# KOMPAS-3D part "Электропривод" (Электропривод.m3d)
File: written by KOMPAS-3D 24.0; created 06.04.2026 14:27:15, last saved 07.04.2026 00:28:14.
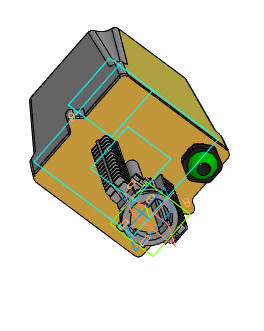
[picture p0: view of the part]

Document properties: Автор: R2D2; Полное имя файла: E:\Работа\Зайцев\Солянка\VSR1-13V-PED-F Клапан запорно-регулирующий DN.ru\DN15\DN15 Kv0.16\исходные материалы\Электропривод.m3d

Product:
- Body: Тело 1  | qty 1
    Масса: 16.873514
- Body: Тело 2  | qty 1
    Масса: 16.873514
- Body: Тело 3  | qty 1
    Масса: 16.873514
- Component [standard]: Hexagon socket head cap screw ISO 4762 - М4 x 10  | qty 1  | Материал: Не определено (density 0 kg/m3); Масса: 0.0018; Рассекать на разрезах: no; source file: C:\Program Files\ASCON\KOMPAS-3D v24\Libs\PolynomLib\DATA\vault\Methods\Kompas\3D\PLib_Screw_DIN_7984_1500.m3d
- Component [standard]: Hexagon socket head cap screw ISO 4762 - М4 x 10  | qty 1  | Материал: Не определено (density 0 kg/m3); Масса: 0.0018; Рассекать на разрезах: no
- Component [standard]: Cheese head screw ISO 7048 - М5 x 10 - H  | qty 1  | Материал: Не определено (density 0 kg/m3); Масса: 0.00255; Рассекать на разрезах: no; source file: C:\Program Files\ASCON\KOMPAS-3D v24\Libs\PolynomLib\DATA\vault\Methods\Kompas\3D\PLib_Screw_ISO_7048_1500.m3d
- Component [standard]: Cheese head screw ISO 7048 - М5 x 10 - H  | qty 1  | Материал: Не определено (density 0 kg/m3); Масса: 0.00255; Рассекать на разрезах: no
- Component [standard]: Hexagon socket set screw ISO 4026 - М4 x 10  | qty 1  | Материал: Не определено (density 0 kg/m3); Масса: 0.0007; Рассекать на разрезах: no; source file: C:\Program Files\ASCON\KOMPAS-3D v24\Libs\PolynomLib\DATA\vault\Methods\Kompas\3D\PLib_Set_Screws_ISO_1100.m3d
- Component [standard]: Hexagon socket set screw ISO 4026 - М4 x 10  | qty 1  | Материал: Не определено (density 0 kg/m3); Масса: 0.0007; Рассекать на разрезах: no
- Component [detail]: Деталь  | qty 1  | Масса: 0.134709; Автор: R2D2; source file: ручка.m3d
- Component [detail]: Деталь  | qty 1  | Масса: 0.106559; Автор: R2D2; source file: кабельный зажим.m3d
- Part/product: Электропривод
    Масса: 0.101125

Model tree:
1. Низ
2. Элемент вращения:1
     Угол 1 = 360
3. Эскиз:4  (with: Ребро.Элемент вращения:1, Грань.Элемент вращения:1)
4. Элемент выдавливания:3
     Расстояние 1 = 25
5. Эскиз:9  (with: Ребро.Элемент выдавливания:3)
6. Элемент выдавливания:6
     Расстояние 2 = 25
7. Эскиз:3  (with: Грань.Элемент вращения:1)
8. Элемент выдавливания:2
9. Эскиз:2  (with: Грань.Элемент вращения:1, Ребро.Элемент выдавливания:2)
10. Элемент выдавливания:1
11. Массив по концентрической сетке:1  (with: Элемент выдавливания:1, Эскиз:2, Грань.Элемент выдавливания:2)  (5 pattern instances)
     Шаг 2 = 360
12. Смещенная плоскость:1
     Расстояние = 269
13. Смещенная плоскость:2
     Расстояние = 125
14. крышка
15. Элемент выдавливания:4
     Расстояние 2 = 144
16. Уклон:1  (with: Грань.Элемент выдавливания:4)
     Угол уклона = 2
17. Эскиз:6  (with: Грань.Элемент выдавливания:4, Вершина.Элемент выдавливания:4)
18. Смещенная плоскость:3  (with: Грань.Элемент выдавливания:4)
     Расстояние = 114
19. Эскиз:7  (with: Ребро.Элемент выдавливания:4)
20. Элемент по сечениям:1
21. Скругление:26  (with: Ребро.Элемент выдавливания:4, Ребро.Элемент по сечениям:1, Грань.Элемент по сечениям:1)
     Радиус = 5
22. Массив по концентрической сетке:3  (with: Элемент по сечениям:1, Эскиз:6, Смещенная плоскость:3, Эскиз:7, Скругление:26)  (4 pattern instances)
     Шаг 2 = 360
23. Скругление:27  (with: Грань.Элемент выдавливания:4)
     Радиус = 5
24. уши  (with: Грань.Элемент выдавливания:4)
25. Элемент выдавливания:5
     Расстояние 2 = 15
26. Скругление:29  (with: Ребро.Элемент выдавливания:5)
     Радиус = 5
27. Эскиз:10  (with: Грань.Элемент выдавливания:4)
28. Элемент выдавливания:7
     Расстояние 1 = 0.5
29. Эскиз:11  (with: Грань.Элемент выдавливания:7, Ребро.Элемент выдавливания:4, Ребро.Скругление:26, Ребро.Элемент выдавливания:5, Ребро.Скругление:29)  (labels: Ребро.Скругление:26.Экземпляр ( 1, 4 ); Ребро.Скругление:26.Экземпляр ( 1, 3 ); Ребро.Скругление:26.Экземпляр ( 1, 2 ))
30. Элемент выдавливания:8
     Расстояние 1 = 5
31. РЕБРО  (with: Ребро.Элемент вращения:1, Ребро.Элемент выдавливания:8)
32. Элемент выдавливания:9
     Расстояние 1 = 3
33. Эскиз:13  (with: Ребро.Элемент выдавливания:9, Ребро.Элемент выдавливания:8, Грань.Элемент вращения:1, Вершина.Элемент вращения:1, Вершина.Элемент выдавливания:9, Ребро.Элемент вращения:1)
34. Элемент выдавливания:10
     Толщина стенки 2 = 2; Расстояние 1 = 20
35. Фаска:6  (with: Ребро.Элемент выдавливания:9)
     Угол = 60; Длина 1 = 10; Длина 2 = 17.3205
36. Эскиз:14  (with: Вершина.Фаска:6, Ребро.Элемент выдавливания:10)
37. Элемент выдавливания:11
     Толщина стенки 1 = 2; Расстояние 1 = 20
38. Скругление:30  (with: Ребро.Элемент выдавливания:11)
     Радиус = 2
39. Массив по сетке:1  (with: Элемент выдавливания:11, Скругление:30, Ребро.Элемент выдавливания:9)  (14 pattern instances)
     Шаг 1 = 7; Угол раствора = 90
40. Эскиз:15  (with: Ребро.Элемент выдавливания:10, Ребро.Фаска:6, Ребро.Элемент выдавливания:11)
41. Элемент выдавливания:12
     Толщина стенки 2 = 2; Расстояние 1 = 20
42. Скругление:31  (with: Ребро.Элемент выдавливания:12)
     Радиус = 2
43. маятник  (with: Ребро.Элемент выдавливания:8)
44. Элемент вращения:2
     Угол 1 = 360
45. Эскиз:17  (with: Ребро.Элемент вращения:2)
46. Элемент выдавливания:13
     Расстояние 1 = 13
47. Скругление:32  (with: Ребро.Элемент выдавливания:13)
     Радиус = 4
48. Эскиз:18  (with: Ребро.Элемент выдавливания:13)
49. Элемент выдавливания:14
     Расстояние 1 = 24
50. Скругление:34  (with: Ребро.Элемент выдавливания:14)
     Радиус = 2
51. Скругление:35  (with: Ребро.Элемент выдавливания:13)
     Радиус = 2
52. Зеркальный массив:1
53. Экземпляр ( 1 )
54. Экземпляр ( 2 )  (with: Элемент выдавливания:9, Массив по сетке:1, Экземпляр ( 1 ), Элемент выдавливания:11, Скругление:30, Элемент выдавливания:12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)
55. Эскиз:19  (with: Грань.Элемент выдавливания:4, Ребро.Скругление:27)
56. Элемент выдавливания:16
     Расстояние 1 = 3
57. Скругление:36  (with: Ребро.Элемент выдавливания:16, Ребро.Скругление:27, Ребро.Скругление:26)  (labels: Ребро.Скругление:26.Экземпляр ( 1, 4 ); Ребро.Скругление:26.Экземпляр ( 1, 3 ); Ребро.Скругление:26.Экземпляр ( 1, 2 ))
     Радиус = 1.5
58. Эскиз:20  (with: Грань.Элемент выдавливания:4, Ребро.Скругление:27)
59. Элемент выдавливания:17
     Расстояние 2 = 10
60. Скругление:37  (with: Грань.Элемент выдавливания:17, Грань.Элемент выдавливания:13, Грань.Скругление:32, Грань.Элемент выдавливания:5, Грань.Скругление:29, Грань.Элемент выдавливания:6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)
     Радиус = 2; Расстояние = -4; Расстояние = -20; Расстояние = 20

Expressions: v238+0.5
Referenced files in C:\Program Files\ASCON\KOMPAS-3D v24\Libs\Pipeline\: StylesTemplate.a3d, TemplateHPH, InsulationStylesTemplate.a3d, Insulation
Referenced files in C:\Program Files\ASCON\KOMPAS-3D v24\Templates\: Констр. чертеж А3 гориз. перв. лист.cdt
Referenced files in E:\Работа\Зайцев\Солянка\VSR1-13V-PED-F Клапан запорно-регулирующий DN.ru\DN15\DN15 Kv0.16\исходные материалы\: , ручка.m3d, кабельный зажим.m3d
Referenced files in C:\Program Files\ASCON\KOMPAS-3D v24\Libs\PolynomLib\DATA\vault\Methods\Kompas\3D\: PLib_Screw_DIN_7984_1500.m3d, PLib_Screw_ISO_7048_1500.m3d, PLib_Set_Screws_ISO_1100.m3d
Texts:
  BOSimple***PART:60499af3-4b6a-c7f5-8cff-0a96383a042f***SHORTLOC:A259_235BDFABBEFC4171[0,7;10;4;-;Undefined]
  BOSimple***PART:5fbac98a-f0ab-87b8-89d4-94a9c7ed4dc2***SHORTLOC:B94B_D4FD7824BC314902[H;0,8;10;5;-;Undefined]
  BOSimple***PART:3ff963e3-104f-0f0e-0a83-42c49b49f7bf***SHORTLOC:A259_4FF597E360DA469F[0,7;10;4;-;Undefined]
  Отводы ГОСТ 17375-2001
  Констр. чертеж А3 гориз. перв. лист.cdt
  Точка начала. Х
  Точка начала. Y
  Точка начала. Z
  Линейный размер с обрывом
  Hexagon socket head cap screw ISO 4762 - М4 x 10 (1)
  Hexagon socket head cap screw ISO 4762 - М4 x 10 (2)
  Cheese head screw ISO 7048 - М5 x 10 - H (1)
  Cheese head screw ISO 7048 - М5 x 10 - H (2)
  Hexagon socket set screw ISO 4026 - М4 x 10 (1)
  Hexagon socket set screw ISO 4026 - М4 x 10 (2)
  Плоскость XY.Начало координат
  Плоскость ZX.Начало координат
